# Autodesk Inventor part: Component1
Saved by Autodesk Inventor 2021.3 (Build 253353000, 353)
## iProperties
Created: 2022-03
Part Number: Component1
Material: Generic
Document SubType Name: Modeling
Designer: Administrator
Density: 1 g/cm^3
Appearance: Default
Title: Component1
Author: Administrator
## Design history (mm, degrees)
feature "Body1"
body "Solid1"
